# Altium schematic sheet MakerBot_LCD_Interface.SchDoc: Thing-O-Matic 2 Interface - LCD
size B; Address1: 189 Schermerhorn St.; Address2: Suite 18E; Address3: Brooklyn, NY 11201; DocumentNumber: MP2305; Revision: A; SheetNumber: 1; SheetTotal: 2; DrawnBy: W. Sakran; PageSetup: Record=PageOptions|CenterHorizontal=True|CenterVertical=True|PrintScale=0.71|XCorrection=1.00|YCorrection=1.00|PrintKind=1|BorderSize=5000000|LeftOffset=0|BottomOffset=0|Orientation=2|PaperLength=1000|PaperWidth=1000|Scale=100|PaperSource=259|PrintQuality=600|MediaType=1|DitherType=10|PaperKind=Letter 8.5x11in.|PrintScaleMode=1
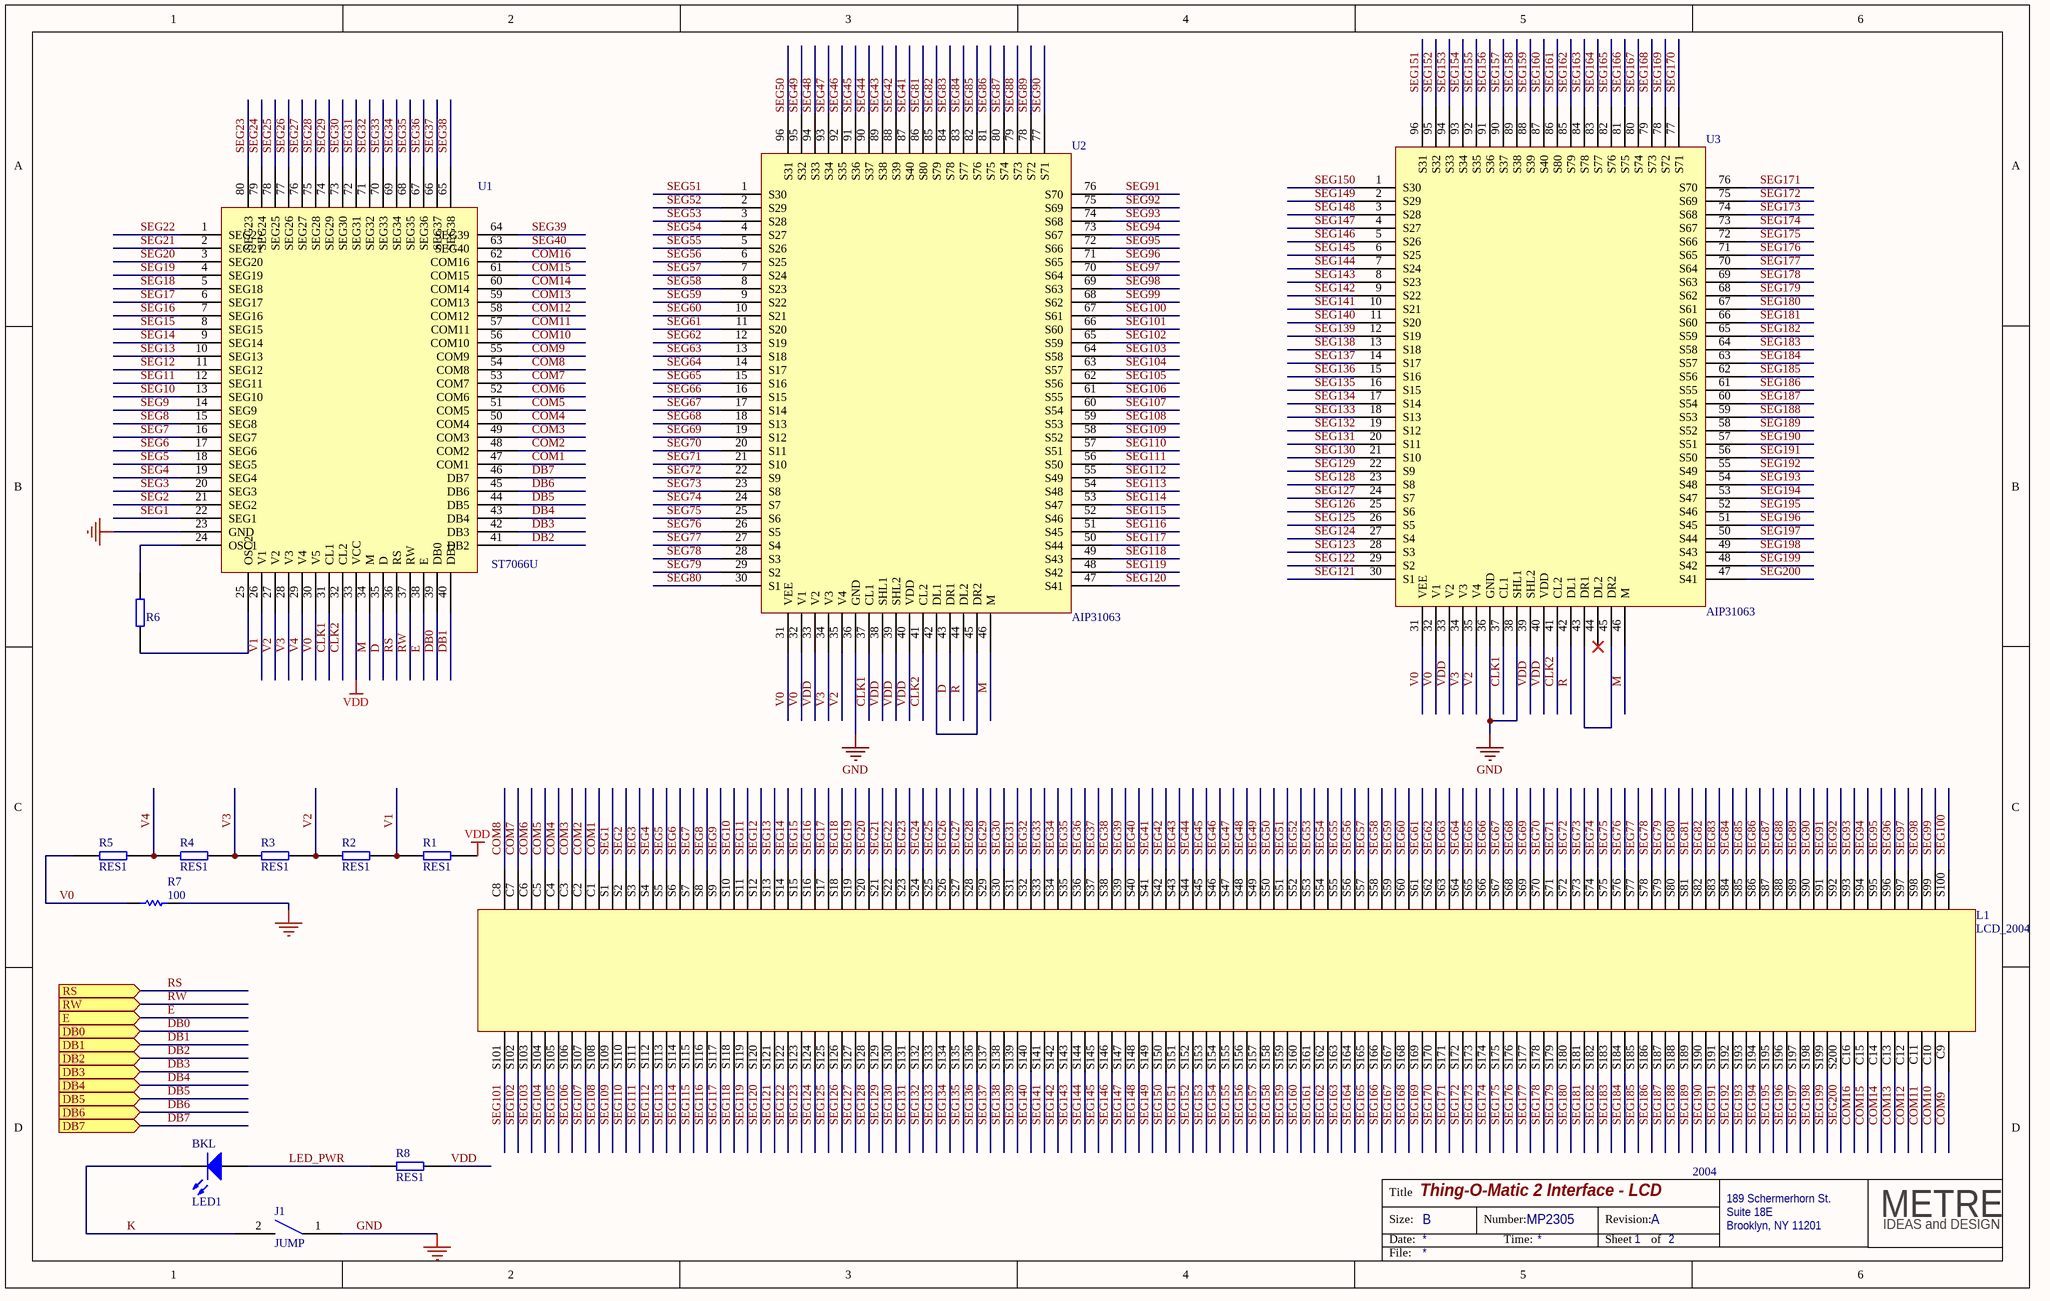
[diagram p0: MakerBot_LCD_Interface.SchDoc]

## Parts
BKL  LED1  [BKL]
J1  JUMP  [JUMP1]
L1  LCD_2004  [2004A-GDS065W]
R1  RES1  [0805]
R2  RES1  [0805]
R3  RES1  [0805]
R4  RES1  [0805]
R5  RES1  [0805]
R6  RES1  [0805]  (value not drawn)
R7  value 100  [RESC2012N]  (hidden comment: Res1)
R8  RES1  [0805]
U1  ST7066U  [S6A0069]
U2  AIP31063  [S6A2067]
U3  AIP31063  [S6A2067]

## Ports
DB0 (in), DB1 (in), DB2 (in), DB3 (in), DB4 (in), DB5 (in), DB6 (in), DB7 (in), E (in), RS (in), RW (in)

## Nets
GND: J1.1 R7.1 U1.23(GND) U2.36(GND) U3.36(GND) U3.38(SHL1)  [also labelled VSS]
VDD: R1.1 R8.1 U1.33(VCC) U2.33(V2) U2.38(SHL1) U2.39(SHL2) U2.40(VDD) U3.33(V2) U3.39(SHL2) U3.40(VDD)
CLK1: U1.31(CL1) U2.37(CL1) U3.37(CL1)
CLK2: U1.32(CL2) U2.41(CL2) U3.41(CL2)
COM1: L1.C1 U1.47(COM1)
COM2: L1.C2 U1.48(COM2)
COM3: L1.C3 U1.49(COM3)
COM4: L1.C4 U1.50(COM4)
COM5: L1.C5 U1.51(COM5)
COM6: L1.C6 U1.52(COM6)
COM7: L1.C7 U1.53(COM7)
COM8: L1.C8 U1.54(COM8)
COM9: L1.C9 U1.55(COM9)
COM10: L1.C10 U1.56(COM10)
COM11: L1.C11 U1.57(COM11)
COM12: L1.C12 U1.58(COM12)
COM13: L1.C13 U1.59(COM13)
COM14: L1.C14 U1.60(COM14)
COM15: L1.C15 U1.61(COM15)
COM16: L1.C16 U1.62(COM16)
D: U1.35(D) U2.43(DR1)
DB0: U1.39(DB0) ; port DB0
DB1: U1.40(DB1) ; port DB1
DB2: U1.41(DB2) ; port DB2
DB3: U1.42(DB3) ; port DB3
DB4: U1.43(DB4) ; port DB4
DB5: U1.44(DB5) ; port DB5
DB6: U1.45(DB6) ; port DB6
DB7: U1.46(DB7) ; port DB7
E: U1.38(E) ; port E
K: BKL.2(K) J1.2
LED_PWR: BKL.1(A) R8.2
M: U1.34(M) U2.46(M) U3.46(M)
R: U2.44(DL2) U3.42(DL1)
RS: U1.36(RS) ; port RS
RW: U1.37(RW) ; port RW
SEG1: L1.S1 U1.22(SEG1)
SEG2: L1.S2 U1.21(SEG2)
SEG3: L1.S3 U1.20(SEG3)
SEG4: L1.S4 U1.19(SEG4)
SEG5: L1.S5 U1.18(SEG5)
SEG6: L1.S6 U1.17(SEG6)
SEG7: L1.S7 U1.16(SEG7)
SEG8: L1.S8 U1.15(SEG8)
SEG9: L1.S9 U1.14(SEG9)
SEG10: L1.S10 U1.13(SEG10)
SEG11: L1.S11 U1.12(SEG11)
SEG12: L1.S12 U1.11(SEG12)
SEG13: L1.S13 U1.10(SEG13)
SEG14: L1.S14 U1.9(SEG14)
SEG15: L1.S15 U1.8(SEG15)
SEG16: L1.S16 U1.7(SEG16)
SEG17: L1.S17 U1.6(SEG17)
SEG18: L1.S18 U1.5(SEG18)
SEG19: L1.S19 U1.4(SEG19)
SEG20: L1.S20 U1.3(SEG20)
SEG21: L1.S21 U1.2(SEG21)
SEG22: L1.S22 U1.1(SEG22)
SEG23: L1.S23 U1.80(SEG23)
SEG24: L1.S24 U1.79(SEG24)
SEG25: L1.S25 U1.78(SEG25)
SEG26: L1.S26 U1.77(SEG26)
SEG27: L1.S27 U1.76(SEG27)
SEG28: L1.S28 U1.75(SEG28)
SEG29: L1.S29 U1.74(SEG29)
SEG30: L1.S30 U1.73(SEG30)
SEG31: L1.S31 U1.72(SEG31)
SEG32: L1.S32 U1.71(SEG32)
SEG33: L1.S33 U1.70(SEG33)
SEG34: L1.S34 U1.69(SEG34)
SEG35: L1.S35 U1.68(SEG35)
SEG36: L1.S36 U1.67(SEG36)
SEG37: L1.S37 U1.66(SEG37)
SEG38: L1.S38 U1.65(SEG38)
SEG39: L1.S39 U1.64(SEG39)
SEG40: L1.S40 U1.63(SEG40)
SEG41: L1.S41 U2.87(S40)
SEG42: L1.S42 U2.88(S39)
SEG43: L1.S43 U2.89(S38)
SEG44: L1.S44 U2.90(S37)
SEG45: L1.S45 U2.91(S36)
SEG46: L1.S46 U2.92(S35)
SEG47: L1.S47 U2.93(S34)
SEG48: L1.S48 U2.94(S33)
SEG49: L1.S49 U2.95(S32)
SEG50: L1.S50 U2.96(S31)
SEG51: L1.S51 U2.1(S30)
SEG52: L1.S52 U2.2(S29)
SEG53: L1.S53 U2.3(S28)
SEG54: L1.S54 U2.4(S27)
SEG55: L1.S55 U2.5(S26)
SEG56: L1.S56 U2.6(S25)
SEG57: L1.S57 U2.7(S24)
SEG58: L1.S58 U2.8(S23)
SEG59: L1.S59 U2.9(S22)
SEG60: L1.S60 U2.10(S21)
SEG61: L1.S61 U2.11(S20)
SEG62: L1.S62 U2.12(S19)
SEG63: L1.S63 U2.13(S18)
SEG64: L1.S64 U2.14(S17)
SEG65: L1.S65 U2.15(S16)
SEG66: L1.S66 U2.16(S15)
SEG67: L1.S67 U2.17(S14)
SEG68: L1.S68 U2.18(S13)
SEG69: L1.S69 U2.19(S12)
SEG70: L1.S70 U2.20(S11)
SEG71: L1.S71 U2.21(S10)
SEG72: L1.S72 U2.22(S9)
SEG73: L1.S73 U2.23(S8)
SEG74: L1.S74 U2.24(S7)
SEG75: L1.S75 U2.25(S6)
SEG76: L1.S76 U2.26(S5)
SEG77: L1.S77 U2.27(S4)
SEG78: L1.S78 U2.28(S3)
SEG79: L1.S79 U2.29(S2)
SEG80: L1.S80 U2.30(S1)
SEG81: L1.S81 U2.86(S80)
SEG82: L1.S82 U2.85(S79)
SEG83: L1.S83 U2.84(S78)
SEG84: L1.S84 U2.83(S77)
SEG85: L1.S85 U2.82(S76)
SEG86: L1.S86 U2.81(S75)
SEG87: L1.S87 U2.80(S74)
SEG88: L1.S88 U2.79(S73)
SEG89: L1.S89 U2.78(S72)
SEG90: L1.S90 U2.77(S71)
SEG91: L1.S91 U2.76(S70)
SEG92: L1.S92 U2.75(S69)
SEG93: L1.S93 U2.74(S68)
SEG94: L1.S94 U2.73(S67)
SEG95: L1.S95 U2.72(S66)
SEG96: L1.S96 U2.71(S65)
SEG97: L1.S97 U2.70(S64)
SEG98: L1.S98 U2.69(S63)
SEG99: L1.S99 U2.68(S62)
SEG100: L1.S100 U2.67(S61)
SEG101: L1.S101 U2.66(S60)
SEG102: L1.S102 U2.65(S59)
SEG103: L1.S103 U2.64(S58)
SEG104: L1.S104 U2.63(S57)
SEG105: L1.S105 U2.62(S56)
SEG106: L1.S106 U2.61(S55)
SEG107: L1.S107 U2.60(S54)
SEG108: L1.S108 U2.59(S53)
SEG109: L1.S109 U2.58(S52)
SEG110: L1.S110 U2.57(S51)
SEG111: L1.S111 U2.56(S50)
SEG112: L1.S112 U2.55(S49)
SEG113: L1.S113 U2.54(S48)
SEG114: L1.S114 U2.53(S47)
SEG115: L1.S115 U2.52(S46)
SEG116: L1.S116 U2.51(S45)
SEG117: L1.S117 U2.50(S44)
SEG118: L1.S118 U2.49(S43)
SEG119: L1.S119 U2.48(S42)
SEG120: L1.S120 U2.47(S41)
SEG121: L1.S121 U3.30(S1)
SEG122: L1.S122 U3.29(S2)
SEG123: L1.S123 U3.28(S3)
SEG124: L1.S124 U3.27(S4)
SEG125: L1.S125 U3.26(S5)
SEG126: L1.S126 U3.25(S6)
SEG127: L1.S127 U3.24(S7)
SEG128: L1.S128 U3.23(S8)
SEG129: L1.S129 U3.22(S9)
SEG130: L1.S130 U3.21(S10)
SEG131: L1.S131 U3.20(S11)
SEG132: L1.S132 U3.19(S12)
SEG133: L1.S133 U3.18(S13)
SEG134: L1.S134 U3.17(S14)
SEG135: L1.S135 U3.16(S15)
SEG136: L1.S136 U3.15(S16)
SEG137: L1.S137 U3.14(S17)
SEG138: L1.S138 U3.13(S18)
SEG139: L1.S139 U3.12(S19)
SEG140: L1.S140 U3.11(S20)
SEG141: L1.S141 U3.10(S21)
SEG142: L1.S142 U3.9(S22)
SEG143: L1.S143 U3.8(S23)
SEG144: L1.S144 U3.7(S24)
SEG145: L1.S145 U3.6(S25)
SEG146: L1.S146 U3.5(S26)
SEG147: L1.S147 U3.4(S27)
SEG148: L1.S148 U3.3(S28)
SEG149: L1.S149 U3.2(S29)
SEG150: L1.S150 U3.1(S30)
SEG151: L1.S151 U3.96(S31)
SEG152: L1.S152 U3.95(S32)
SEG153: L1.S153 U3.94(S33)
SEG154: L1.S154 U3.93(S34)
SEG155: L1.S155 U3.92(S35)
SEG156: L1.S156 U3.91(S36)
SEG157: L1.S157 U3.90(S37)
SEG158: L1.S158 U3.89(S38)
SEG159: L1.S159 U3.88(S39)
SEG160: L1.S160 U3.87(S40)
SEG161: L1.S161 U3.86(S80)
SEG162: L1.S162 U3.85(S79)
SEG163: L1.S163 U3.84(S78)
SEG164: L1.S164 U3.83(S77)
SEG165: L1.S165 U3.82(S76)
SEG166: L1.S166 U3.81(S75)
SEG167: L1.S167 U3.80(S74)
SEG168: L1.S168 U3.79(S73)
SEG169: L1.S169 U3.78(S72)
SEG170: L1.S170 U3.77(S71)
SEG171: L1.S171 U3.76(S70)
SEG172: L1.S172 U3.75(S69)
SEG173: L1.S173 U3.74(S68)
SEG174: L1.S174 U3.73(S67)
SEG175: L1.S175 U3.72(S66)
SEG176: L1.S176 U3.71(S65)
SEG177: L1.S177 U3.70(S64)
SEG178: L1.S178 U3.69(S63)
SEG179: L1.S179 U3.68(S62)
SEG180: L1.S180 U3.67(S61)
SEG181: L1.S181 U3.66(S60)
SEG182: L1.S182 U3.65(S59)
SEG183: L1.S183 U3.64(S58)
SEG184: L1.S184 U3.63(S57)
SEG185: L1.S185 U3.62(S56)
SEG186: L1.S186 U3.61(S55)
SEG187: L1.S187 U3.60(S54)
SEG188: L1.S188 U3.59(S53)
SEG189: L1.S189 U3.58(S52)
SEG190: L1.S190 U3.57(S51)
SEG191: L1.S191 U3.56(S50)
SEG192: L1.S192 U3.55(S49)
SEG193: L1.S193 U3.54(S48)
SEG194: L1.S194 U3.53(S47)
SEG195: L1.S195 U3.52(S46)
SEG196: L1.S196 U3.51(S45)
SEG197: L1.S197 U3.50(S44)
SEG198: L1.S198 U3.49(S43)
SEG199: L1.S199 U3.48(S42)
SEG200: L1.S200 U3.47(S41)
V0: R5.2 R7.2 U1.30(V5) U2.31(VEE) U2.32(V1) U3.31(VEE) U3.32(V1)
V1: R1.2 R2.1 U1.26(V1)
V2: R2.2 R3.1 U1.27(V2) U2.35(V4) U3.35(V4)
V3: R3.2 R4.1 U1.28(V3) U2.34(V3) U3.34(V3)
V4: R4.2 R5.1 U1.29(V4)
NetR6_1: R6.1 U1.24(OSC1)
NetR6_2: R6.2 U1.25(OSC2)
NetU2_42: U2.42(DL1) U2.45(DR2)
NetU3_43: U3.43(DR1) U3.45(DR2)

Not connected (* = marked no-connect by the designer): U3 44(DL2)*

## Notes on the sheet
- 2004

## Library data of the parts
BKL = LED1: Typical RED GaAs LED
R7 = Res1: Resistor
U1 = KS0066U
